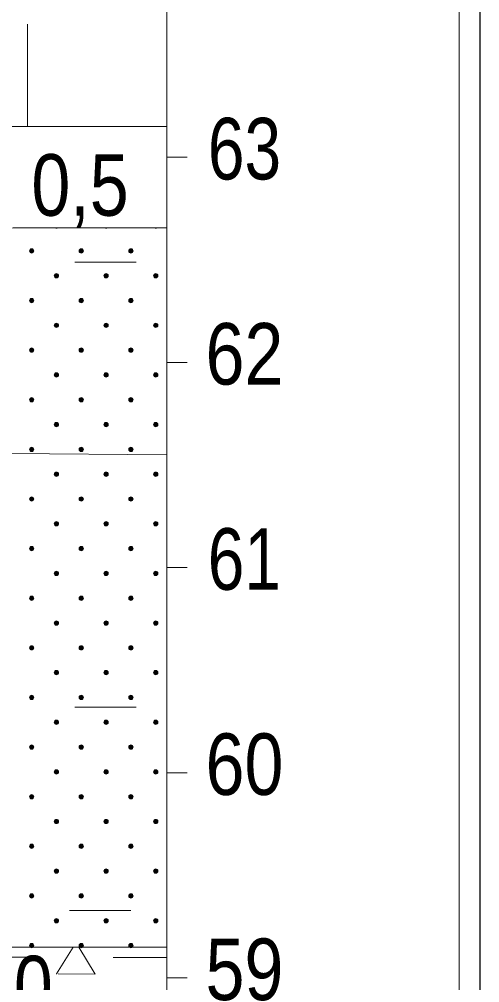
# Model space of a CAD drawing. Extents: x 640104 to 640970, y 6442278 to 6442689.
# Drawn here: x 640947.87 to 640970.3, y 6442508.71 to 6442555.67 of the extents above; entities that cross this region are included whole.
import ezdxf
from ezdxf.enums import TextEntityAlignment as Align

# ---------------------------------------------------------------- set-up
doc = ezdxf.new("R2010")
doc.units = 0
doc.header["$LTSCALE"] = 1.2
for name, color, linetype, lineweight in [('30', 7, 'Continuous', 13), ('31', 7, 'Continuous', 13), ('32', 7, 'Continuous', 25), ('34', 7, 'Continuous', 25), ('35', 7, 'Continuous', 35), ('45', 7, 'Continuous', 13), ('46', 7, 'Continuous', 13), ('47', 7, 'Continuous', 13), ('50', 7, 'Continuous', 13)]:
    doc.layers.add(name, color=color, linetype=linetype, lineweight=lineweight)

msp = doc.modelspace()

# ---------------------------------------------------------------- hatches: boundary and pattern name
at = {"layer": '45'}
for points in [[(640948.547, 6442544.45, 1), (640948.398, 6442544.301, 1)], [(640950.965, 6442544.45, 1), (640950.817, 6442544.301, 1)], [(640953.384, 6442544.45, 1), (640953.235, 6442544.301, 1)], [(640949.756, 6442543.241, 1), (640949.608, 6442543.092, 1)], [(640952.174, 6442543.241, 1), (640952.026, 6442543.092, 1)], [(640954.593, 6442543.241, 1), (640954.444, 6442543.092, 1)], [(640948.547, 6442542.031, 1), (640948.398, 6442541.883, 1)], [(640950.965, 6442542.031, 1), (640950.817, 6442541.883, 1)], [(640953.384, 6442542.031, 1), (640953.235, 6442541.883, 1)], [(640949.756, 6442540.822, 1), (640949.608, 6442540.674, 1)], [(640952.174, 6442540.822, 1), (640952.026, 6442540.674, 1)], [(640954.593, 6442540.822, 1), (640954.444, 6442540.674, 1)], [(640948.547, 6442539.613, 1), (640948.398, 6442539.465, 1)], [(640950.965, 6442539.613, 1), (640950.817, 6442539.465, 1)], [(640953.384, 6442539.613, 1), (640953.235, 6442539.465, 1)], [(640949.756, 6442538.404, 1), (640949.608, 6442538.255, 1)], [(640952.174, 6442538.404, 1), (640952.026, 6442538.255, 1)], [(640954.593, 6442538.404, 1), (640954.444, 6442538.255, 1)], [(640948.547, 6442537.195, 1), (640948.398, 6442537.046, 1)], [(640950.965, 6442537.195, 1), (640950.817, 6442537.046, 1)], [(640953.384, 6442537.195, 1), (640953.235, 6442537.046, 1)], [(640949.756, 6442535.986, 1), (640949.608, 6442535.837, 1)], [(640952.174, 6442535.986, 1), (640952.026, 6442535.837, 1)], [(640954.593, 6442535.986, 1), (640954.444, 6442535.837, 1)], [(640948.547, 6442534.776, 1), (640948.398, 6442534.628, 1)], [(640950.965, 6442534.776, 1), (640950.817, 6442534.628, 1)], [(640953.384, 6442534.776, 1), (640953.235, 6442534.628, 1)], [(640949.756, 6442533.567, 1), (640949.608, 6442533.419, 1)], [(640952.174, 6442533.567, 1), (640952.026, 6442533.419, 1)], [(640954.593, 6442533.567, 1), (640954.444, 6442533.419, 1)], [(640948.547, 6442532.358, 1), (640948.398, 6442532.21, 1)], [(640950.965, 6442532.358, 1), (640950.817, 6442532.21, 1)], [(640953.384, 6442532.358, 1), (640953.235, 6442532.21, 1)], [(640949.756, 6442531.149, 1), (640949.608, 6442531, 1)], [(640952.174, 6442531.149, 1), (640952.026, 6442531, 1)], [(640954.593, 6442531.149, 1), (640954.444, 6442531, 1)], [(640948.547, 6442529.94, 1), (640948.398, 6442529.791, 1)], [(640950.965, 6442529.94, 1), (640950.817, 6442529.791, 1)], [(640953.384, 6442529.94, 1), (640953.235, 6442529.791, 1)], [(640949.756, 6442528.731, 1), (640949.608, 6442528.582, 1)], [(640952.174, 6442528.731, 1), (640952.026, 6442528.582, 1)], [(640954.593, 6442528.731, 1), (640954.444, 6442528.582, 1)], [(640948.547, 6442527.522, 1), (640948.398, 6442527.373, 1)], [(640950.965, 6442527.522, 1), (640950.817, 6442527.373, 1)], [(640953.384, 6442527.522, 1), (640953.235, 6442527.373, 1)], [(640949.756, 6442526.312, 1), (640949.608, 6442526.164, 1)], [(640952.174, 6442526.312, 1), (640952.026, 6442526.164, 1)], [(640954.593, 6442526.312, 1), (640954.444, 6442526.164, 1)], [(640948.547, 6442525.103, 1), (640948.398, 6442524.955, 1)], [(640950.965, 6442525.103, 1), (640950.817, 6442524.955, 1)], [(640953.384, 6442525.103, 1), (640953.235, 6442524.955, 1)], [(640949.756, 6442523.894, 1), (640949.608, 6442523.746, 1)], [(640952.174, 6442523.894, 1), (640952.026, 6442523.746, 1)], [(640954.593, 6442523.894, 1), (640954.444, 6442523.746, 1)], [(640948.547, 6442522.685, 1), (640948.398, 6442522.536, 1)], [(640950.965, 6442522.685, 1), (640950.817, 6442522.536, 1)], [(640953.384, 6442522.685, 1), (640953.235, 6442522.536, 1)], [(640949.756, 6442521.476, 1), (640949.608, 6442521.327, 1)], [(640952.174, 6442521.476, 1), (640952.026, 6442521.327, 1)], [(640954.593, 6442521.476, 1), (640954.444, 6442521.327, 1)], [(640948.547, 6442520.267, 1), (640948.398, 6442520.118, 1)], [(640950.965, 6442520.267, 1), (640950.817, 6442520.118, 1)], [(640953.384, 6442520.267, 1), (640953.235, 6442520.118, 1)], [(640949.756, 6442519.057, 1), (640949.608, 6442518.909, 1)], [(640952.174, 6442519.057, 1), (640952.026, 6442518.909, 1)], [(640954.593, 6442519.057, 1), (640954.444, 6442518.909, 1)], [(640948.547, 6442517.848, 1), (640948.398, 6442517.7, 1)], [(640950.965, 6442517.848, 1), (640950.817, 6442517.7, 1)], [(640953.384, 6442517.848, 1), (640953.235, 6442517.7, 1)], [(640949.756, 6442516.639, 1), (640949.608, 6442516.491, 1)], [(640952.174, 6442516.639, 1), (640952.026, 6442516.491, 1)], [(640954.593, 6442516.639, 1), (640954.444, 6442516.491, 1)], [(640948.547, 6442515.43, 1), (640948.398, 6442515.282, 1)], [(640950.965, 6442515.43, 1), (640950.817, 6442515.282, 1)], [(640953.384, 6442515.43, 1), (640953.235, 6442515.282, 1)], [(640949.756, 6442514.221, 1), (640949.608, 6442514.072, 1)], [(640952.174, 6442514.221, 1), (640952.026, 6442514.072, 1)], [(640954.593, 6442514.221, 1), (640954.444, 6442514.072, 1)], [(640948.547, 6442513.012, 1), (640948.398, 6442512.863, 1)], [(640950.965, 6442513.012, 1), (640950.817, 6442512.863, 1)], [(640953.384, 6442513.012, 1), (640953.235, 6442512.863, 1)], [(640949.756, 6442511.803, 1), (640949.608, 6442511.654, 1)], [(640952.174, 6442511.803, 1), (640952.026, 6442511.654, 1)], [(640954.593, 6442511.803, 1), (640954.444, 6442511.654, 1)], [(640948.547, 6442510.593, 1), (640948.398, 6442510.445, 1)], [(640950.965, 6442510.593, 1), (640950.817, 6442510.445, 1)], [(640953.384, 6442510.593, 1), (640953.235, 6442510.445, 1)]]:
    msp.add_hatch(color=256, dxfattribs=at).paths.add_polyline_path(points)

# ---------------------------------------------------------------- linework, layer by layer
at = {"layer": '30'}
for p, q in [((640955.05, 6442488.94), (640955.05, 6442658.94)), ((640955.05, 6442548.94), (640956.05, 6442548.94)), ((640955.05, 6442538.94), (640956.05, 6442538.94)), ((640955.05, 6442528.94), (640956.05, 6442528.94)), ((640955.05, 6442518.94), (640956.05, 6442518.94)), ((640955.05, 6442508.94), (640956.05, 6442508.94))]:
    msp.add_line(p, q, dxfattribs=at)
at = {"layer": '31'}
for points in [[(640553.71, 6442558.56), (640570.07, 6442558.94), (640649.85, 6442563.98), (640763.79, 6442536.22), (640808.67, 6442524.48), (640822.17, 6442520.94), (640837.77, 6442517.67), (640873.2, 6442509.45), (640884.27, 6442508.94), (640895.27, 6442508.94), (640947.47, 6442510.44), (640955.05, 6442510.44)], [(640905.53, 6442550.44), (640907.99, 6442550.17), (640919.96, 6442549.99), (640926.08, 6442550.01), (640947.47, 6442550.44), (640955.05, 6442550.44)], [(640901.98, 6442546.85), (640907.61, 6442545.9), (640917.36, 6442545.11), (640937.9, 6442545.35), (640947.57, 6442545.5), (640955.05, 6442545.5)]]:
    msp.add_lwpolyline(points, dxfattribs=at)
at = {"layer": '34', "lineweight": 13}
msp.add_lwpolyline([(640718.51, 6442547.61), (640760.64, 6442545.05), (640822.17, 6442540.94), (640861.08, 6442538.41), (640873.26, 6442537.95), (640895.2, 6442536.39), (640947.44, 6442534.5), (640955.05, 6442534.43)], dxfattribs=at)
at = {"layer": '35', "lineweight": 13}
msp.add_line((640948.27, 6442550.44), (640948.27, 6442555.43), dxfattribs=at)
at = {"layer": '45'}
for centre in [(640948.473, 6442544.375), (640950.891, 6442544.375), (640953.309, 6442544.375), (640949.682, 6442543.166), (640952.1, 6442543.166), (640954.519, 6442543.166), (640948.473, 6442541.957), (640950.891, 6442541.957), (640953.309, 6442541.957), (640949.682, 6442540.748), (640952.1, 6442540.748), (640954.519, 6442540.748), (640948.473, 6442539.539), (640950.891, 6442539.539), (640953.309, 6442539.539), (640949.682, 6442538.33), (640952.1, 6442538.33), (640954.519, 6442538.33), (640948.473, 6442537.121), (640950.891, 6442537.121), (640953.309, 6442537.121), (640949.682, 6442535.911), (640952.1, 6442535.911), (640954.519, 6442535.911), (640948.473, 6442534.702), (640950.891, 6442534.702), (640953.309, 6442534.702), (640949.682, 6442533.493), (640952.1, 6442533.493), (640954.519, 6442533.493), (640948.473, 6442532.284), (640950.891, 6442532.284), (640953.309, 6442532.284), (640949.682, 6442531.075), (640952.1, 6442531.075), (640954.519, 6442531.075), (640948.473, 6442529.866), (640950.891, 6442529.866), (640953.309, 6442529.866), (640949.682, 6442528.656), (640952.1, 6442528.656), (640954.519, 6442528.656), (640948.473, 6442527.447), (640950.891, 6442527.447), (640953.309, 6442527.447), (640949.682, 6442526.238), (640952.1, 6442526.238), (640954.519, 6442526.238), (640948.473, 6442525.029), (640950.891, 6442525.029), (640953.309, 6442525.029), (640949.682, 6442523.82), (640952.1, 6442523.82), (640954.519, 6442523.82), (640948.473, 6442522.611), (640950.891, 6442522.611), (640953.309, 6442522.611), (640949.682, 6442521.402), (640952.1, 6442521.402), (640954.519, 6442521.402), (640948.473, 6442520.192), (640950.891, 6442520.192), (640953.309, 6442520.192), (640949.682, 6442518.983), (640952.1, 6442518.983), (640954.519, 6442518.983), (640948.473, 6442517.774), (640950.891, 6442517.774), (640953.309, 6442517.774), (640949.682, 6442516.565), (640952.1, 6442516.565), (640954.519, 6442516.565), (640948.473, 6442515.356), (640950.891, 6442515.356), (640953.309, 6442515.356), (640949.682, 6442514.147), (640952.1, 6442514.147), (640954.519, 6442514.147), (640948.473, 6442512.937), (640950.891, 6442512.937), (640953.309, 6442512.937), (640949.682, 6442511.728), (640952.1, 6442511.728), (640954.519, 6442511.728), (640948.473, 6442510.519), (640950.891, 6442510.519), (640953.309, 6442510.519)]:
    msp.add_circle(centre, 0.105, dxfattribs=at)
for centre in [(640949.682, 6442545.585), (640952.1, 6442545.585), (640954.519, 6442545.585)]:
    msp.add_arc(centre, 0.105, 229.696, 310.304, dxfattribs=at)
at = {"layer": '46'}
for p, q in [((640948.74, 6442509.95), (640945.14, 6442509.95)), ((640955.05, 6442509.94), (640952.44, 6442509.94))]:
    msp.add_line(p, q, dxfattribs=at)
for points in [[(640949.68, 6442509.12), (640949.68, 6442509.14), (640950.49, 6442510.44)], [(640950.77, 6442510.44), (640951.56, 6442509.13), (640949.76, 6442509.14)]]:
    msp.add_lwpolyline(points, dxfattribs=at)
at = {"layer": '47'}
for p, q in [((640950.57, 6442543.82), (640953.57, 6442543.82)), ((640950.57, 6442522.13), (640953.57, 6442522.13)), ((640950.31, 6442512.23), (640953.31, 6442512.23))]:
    msp.add_line(p, q, dxfattribs=at)
at = {"layer": '50', "lineweight": 25}
msp.add_lwpolyline([(640103.56, 6442688.99), (640970.3, 6442688.99), (640970.3, 6442282.54), (640103.56, 6442282.54)], close=True, dxfattribs=at)
at = {"layer": '50'}
msp.add_lwpolyline([(640104.56, 6442687.99), (640969.3, 6442687.99), (640969.3, 6442283.54), (640104.56, 6442283.54)], close=True, dxfattribs=at)

# ---------------------------------------------------------------- texts
at = {"layer": '30'}
for s, width, p in [('63', 0.8, (640958.84, 6442547.86)), ('62', 0.85, (640958.84, 6442537.86)), ('61', 0.8, (640958.835, 6442527.86)), ('60', 0.85, (640958.84, 6442517.86)), ('59', 0.85, (640958.84, 6442507.86))]:
    msp.add_text(s, height=3, dxfattribs=dict(at, width=width)).set_placement(p, align=Align.CENTER)
at = {"layer": '32', "width": 0.85}
for s, p in [('0,5', (640950.83, 6442546.09)), ('4,0', (640947.135, 6442507.02))]:
    msp.add_text(s, height=3, dxfattribs=at).set_placement(p, align=Align.CENTER)

doc.saveas('drawing.dxf')
